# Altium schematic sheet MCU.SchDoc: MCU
size A3; CompanyName: Hitex GmbH; Address1: Greschbachstr. 12; Address2: 76229 Karlsruhe, Germany; Address3: www.hitex.com; DocumentNumber: 2; SheetNumber: 9; SheetTotal: 9; PageSetup: Record=PageOptions¦CenterHorizontal=True¦CenterVertical=True¦PrintScale=1.04¦XCorrection=1.00¦YCorrection=1.00¦PrintKind=0¦BorderSize=5000000¦LeftOffset=0¦BottomOffset=0¦Orientation=2¦PaperLength=1000¦PaperWidth=1000¦Scale=100¦PaperSource=7¦PrintQuality=1200¦MediaType=1¦DitherType=10¦PaperKind=A3¦PrintScaleMode=1
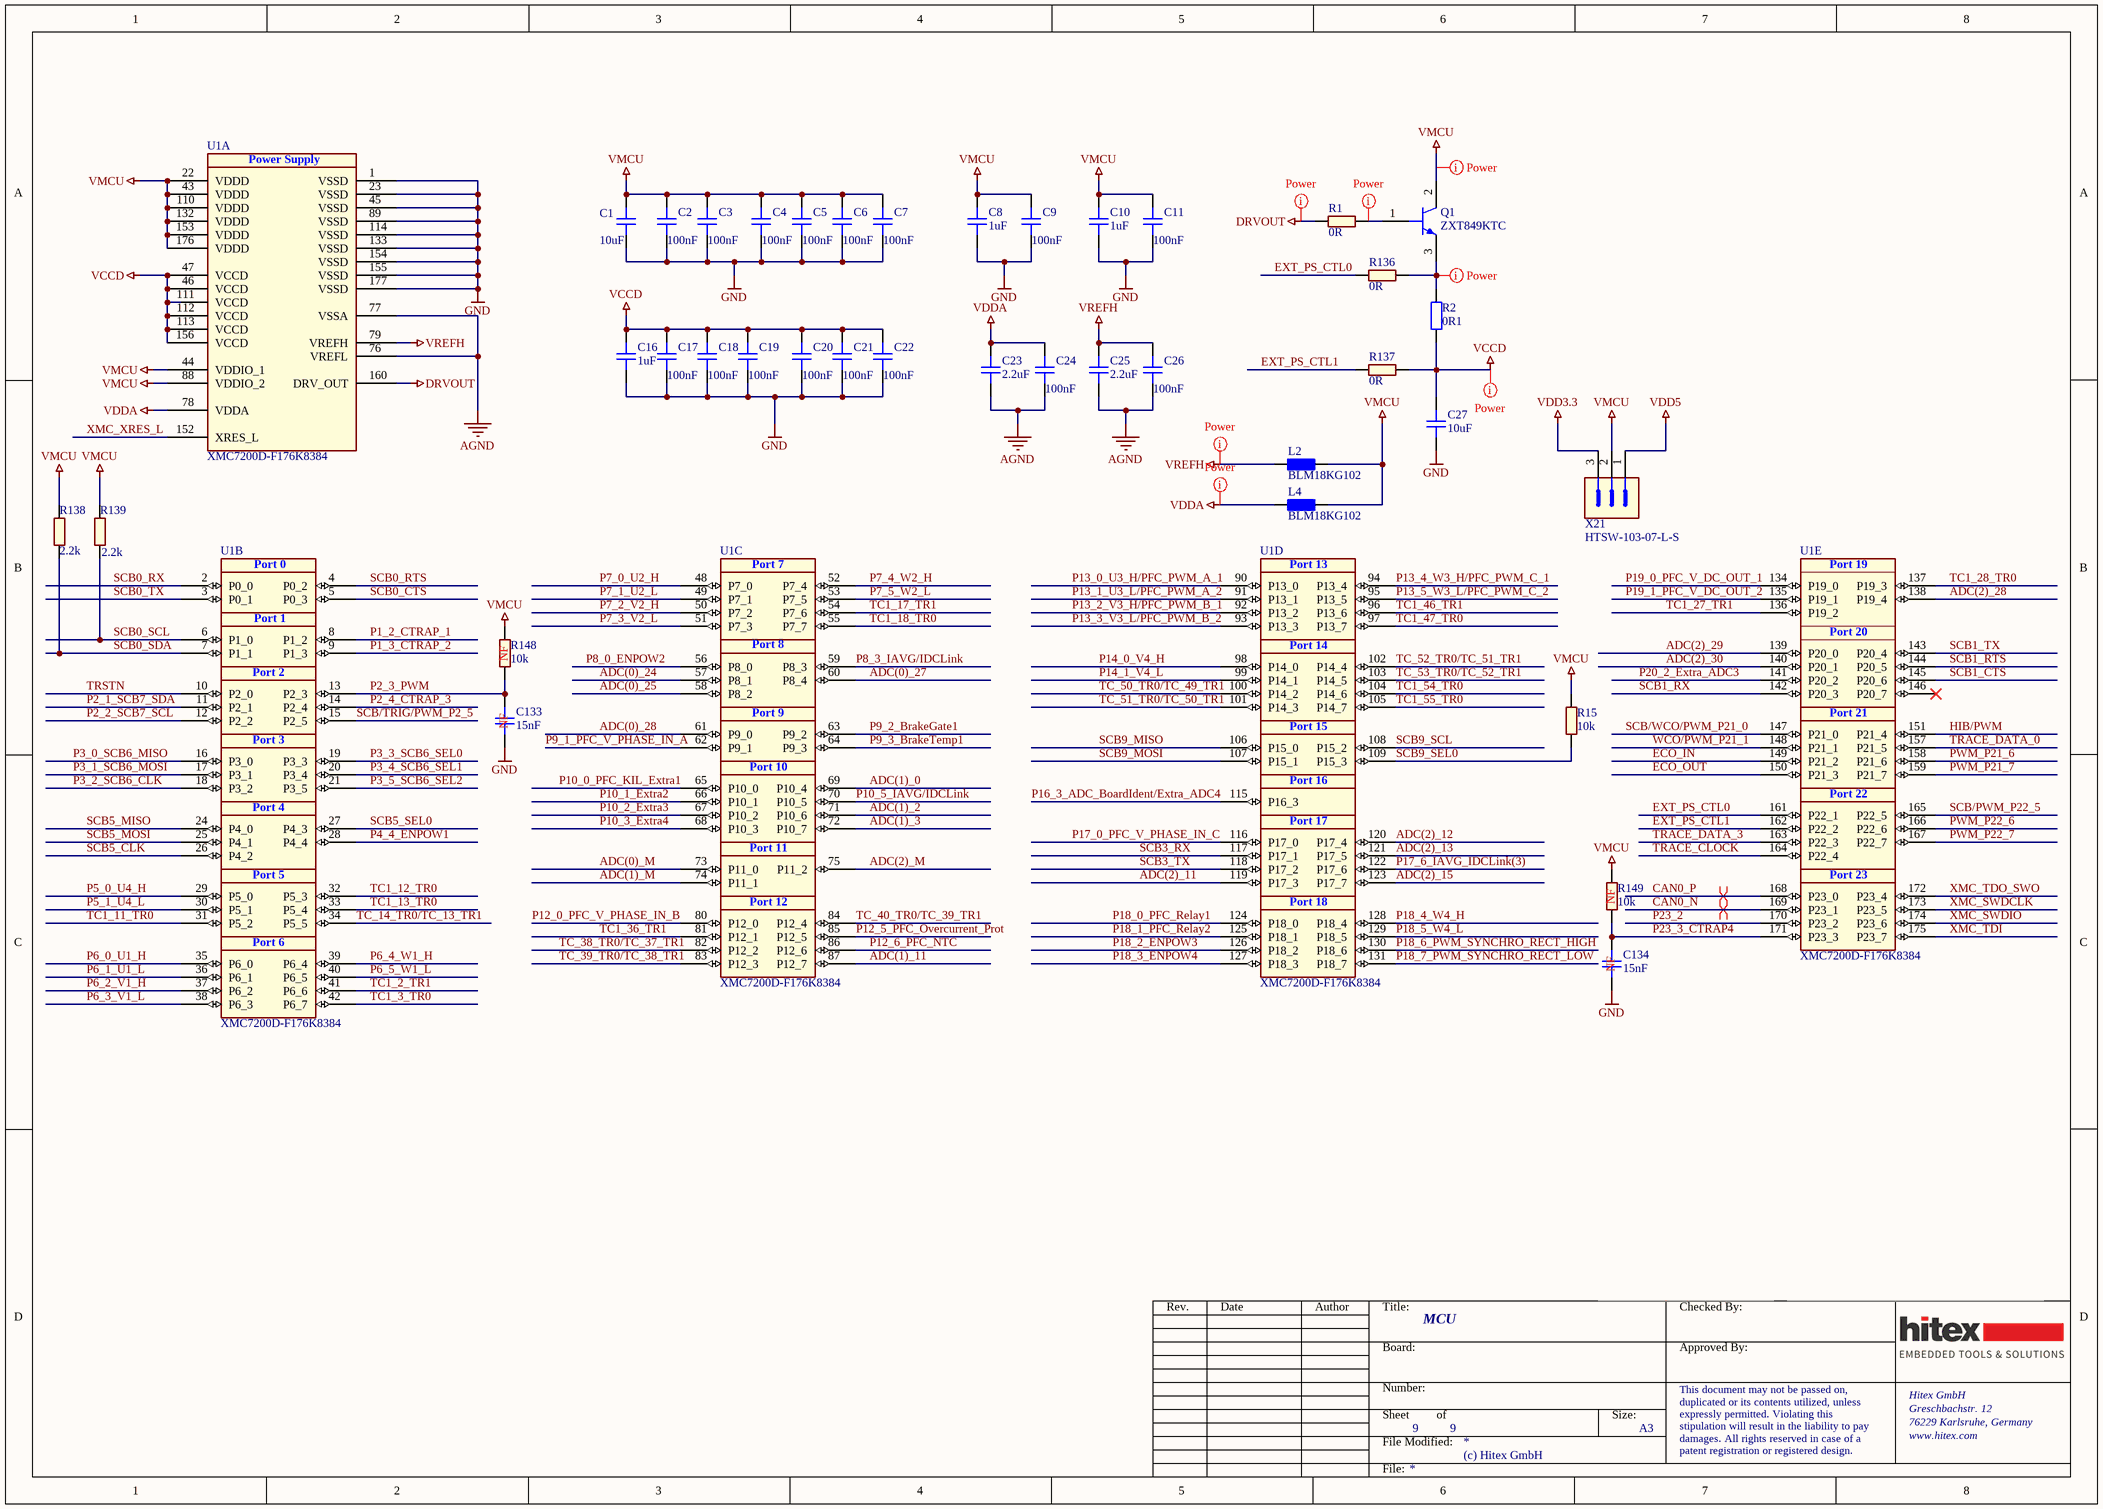
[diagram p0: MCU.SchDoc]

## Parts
C1  10uF  [CAPC3216X180N]
C2  100nF  [CAPC1005X60N]
C3  100nF  [CAPC1005X60N]
C4  100nF  [CAPC1005X60N]
C5  100nF  [CAPC1005X60N]
C6  100nF  [CAPC1005X60N]
C7  100nF  [CAPC1005X60N]
C8  1uF  [CAPC1608X90N-1]
C9  100nF  [CAPC1005X60N]
C10  1uF  [CAPC1608X90N-1]
C11  100nF  [CAPC1005X60N]
C16  1uF  [CAPC1608X90N-1]
C17  100nF  [CAPC1005X60N]
C18  100nF  [CAPC1005X60N]
C19  100nF  [CAPC1005X60N]
C20  100nF  [CAPC1005X60N]
C21  100nF  [CAPC1005X60N]
C22  100nF  [CAPC1005X60N]
C23  2.2uF  [CAPC2013X140N-1]
C24  100nF  [CAPC1005X60N]
C25  2.2uF  [CAPC2013X140N-1]
C26  100nF  [CAPC1005X60N]
C27  10uF  [CAPC3216X180N]
C133  15nF  [CAPC1005X55N-0]
C134  15nF  [CAPC1005X55N-0]
L2  BLM18KG102  [INDC1608N]
L4  BLM18KG102  [INDC1608N]
Q1  ZXT849KTC  [TO229P991X252-3N]
R1  0R  [RESC1005X03N]
R2  0R1  [RESC3216N]
R15  10k  [RESC1005X40N]
R136  0R  [RESC1005X03N]
R137  0R  [RESC1005X03N]
R138  2.2k  [RESC1005X40N]
R139  2.2k  [RESC1005X40N]
R148  10k  [RESC1005X40N]
R149  10k  [RESC1005X40N]
U1  XMC7200D-F176K8384  [QFP50P2600X2600X170-177N]  (parts A,B,C,D,E of 5)
X21  HTSW-103-07-L-S  [CON-M-THT-HTSW-103-07-L-S]

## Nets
AGND: C23.1 C24.1 C25.1 C26.1 U1.76(VREFL) U1.77(VSSA)
DRVOUT: R1.1 U1.160(DRV_OUT)
GND: C1.1 C2.1 C3.1 C4.1 C5.1 C6.1 C7.1 C8.1 C9.1 C10.1 C11.1 C16.1 C17.1 C18.1 C19.1 C20.1 C21.1 C22.1 C27.1 C133.2 C134.2 U1.1(VSSD) U1.23(VSSD) U1.45(VSSD) U1.89(VSSD) U1.114(VSSD) U1.133(VSSD) U1.154(VSSD) U1.155(VSSD) U1.177(VSSD)
VCCD: C16.2 C17.2 C18.2 C19.2 C20.2 C21.2 C22.2 C27.2 R2.1 R137.2 U1.46(VCCD) U1.47(VCCD) U1.111(VCCD) U1.112(VCCD) U1.113(VCCD) U1.156(VCCD)
VDD3.3: X21.3
VDD5: X21.1
VDDA: C23.2 C24.2 L4.1 U1.78(VDDA)
VMCU: C1.2 C2.2 C3.2 C4.2 C5.2 C6.2 C7.2 C8.2 C9.2 C10.2 C11.2 L2.2 L4.2 Q1.2(COLLECTOR) R15.2 R138.2 R139.2 R148.2 R149.2 U1.22(VDDD) U1.43(VDDD) U1.44(VDDIO_1) U1.88(VDDIO_2) U1.110(VDDD) U1.132(VDDD) U1.153(VDDD) U1.176(VDDD) X21.2
VREFH: C25.2 C26.2 L2.1 U1.79(VREFH)
ADC(0)_24: U1.57(P8_1)
ADC(0)_25: U1.58(P8_2)
ADC(0)_27: U1.60(P8_4)
ADC(0)_28: U1.61(P9_0)
ADC(0)_M: U1.73(P11_0)
ADC(1)_0: U1.69(P10_4)
ADC(1)_2: U1.71(P10_6)
ADC(1)_3: U1.72(P10_7)
ADC(1)_11: U1.87(P12_7)
ADC(1)_M: U1.74(P11_1)
ADC(2)_11: U1.119(P17_3)
ADC(2)_12: U1.120(P17_4)
ADC(2)_13: U1.121(P17_5)
ADC(2)_15: U1.123(P17_7)
ADC(2)_28: U1.138(P19_4)
ADC(2)_29: U1.139(P20_0)
ADC(2)_30: U1.140(P20_1)
ADC(2)_M: U1.75(P11_2)
CAN0_N: U1.169(P23_1)
CAN0_P: U1.168(P23_0)
ECO_IN: U1.149(P21_2)
ECO_OUT: U1.150(P21_3)
EXT_PS_CTL0: R136.1 U1.161(P22_1)
EXT_PS_CTL1: R137.1 U1.162(P22_2)
HIB/PWM: U1.151(P21_4)
P1_2_CTRAP_1: U1.8(P1_2)
P1_3_CTRAP_2: U1.9(P1_3)
P2_1_SCB7_SDA: U1.11(P2_1)
P2_2_SCB7_SCL: U1.12(P2_2)
P2_3_PWM: C133.1 R148.1 U1.13(P2_3)
P2_4_CTRAP_3: U1.14(P2_4)
P3_0_SCB6_MISO: U1.16(P3_0)
P3_1_SCB6_MOSI: U1.17(P3_1)
P3_2_SCB6_CLK: U1.18(P3_2)
P3_3_SCB6_SEL0: U1.19(P3_3)
P3_4_SCB6_SEL1: U1.20(P3_4)
P3_5_SCB6_SEL2: U1.21(P3_5)
P4_4_ENPOW1: U1.28(P4_4)
P5_0_U4_H: U1.29(P5_0)
P5_1_U4_L: U1.30(P5_1)
P6_0_U1_H: U1.35(P6_0)
P6_1_U1_L: U1.36(P6_1)
P6_2_V1_H: U1.37(P6_2)
P6_3_V1_L: U1.38(P6_3)
P6_4_W1_H: U1.39(P6_4)
P6_5_W1_L: U1.40(P6_5)
P7_0_U2_H: U1.48(P7_0)
P7_1_U2_L: U1.49(P7_1)
P7_2_V2_H: U1.50(P7_2)
P7_3_V2_L: U1.51(P7_3)
P7_4_W2_H: U1.52(P7_4)
P7_5_W2_L: U1.53(P7_5)
P8_0_ENPOW2: U1.56(P8_0)
P8_3_IAVG/IDCLink: U1.59(P8_3)
P9_1_PFC_V_PHASE_IN_A: U1.62(P9_1)
P9_2_BrakeGate1: U1.63(P9_2)
P9_3_BrakeTemp1: U1.64(P9_3)
P10_0_PFC_KIL_Extra1: U1.65(P10_0)
P10_1_Extra2: U1.66(P10_1)
P10_2_Extra3: U1.67(P10_2)
P10_3_Extra4: U1.68(P10_3)
P10_5_IAVG/IDCLink: U1.70(P10_5)
P12_0_PFC_V_PHASE_IN_B: U1.80(P12_0)
P12_5_PFC_Overcurrent_Prot: U1.85(P12_5)
P12_6_PFC_NTC: U1.86(P12_6)
P13_0_U3_H/PFC_PWM_A_1: U1.90(P13_0)
P13_1_U3_L/PFC_PWM_A_2: U1.91(P13_1)
P13_2_V3_H/PFC_PWM_B_1: U1.92(P13_2)
P13_3_V3_L/PFC_PWM_B_2: U1.93(P13_3)
P13_4_W3_H/PFC_PWM_C_1: U1.94(P13_4)
P13_5_W3_L/PFC_PWM_C_2: U1.95(P13_5)
P14_0_V4_H: U1.98(P14_0)
P14_1_V4_L: U1.99(P14_1)
P16_3_ADC_BoardIdent/Extra_ADC4: U1.115(P16_3)
P17_0_PFC_V_PHASE_IN_C: U1.116(P17_0)
P17_6_IAVG_IDCLink(3): U1.122(P17_6)
P18_0_PFC_Relay1: U1.124(P18_0)
P18_1_PFC_Relay2: U1.125(P18_1)
P18_2_ENPOW3: U1.126(P18_2)
P18_3_ENPOW4: U1.127(P18_3)
P18_4_W4_H: U1.128(P18_4)
P18_5_W4_L: U1.129(P18_5)
P18_6_PWM_SYNCHRO_RECT_HIGH: U1.130(P18_6)
P18_7_PWM_SYNCHRO_RECT_LOW: U1.131(P18_7)
P19_0_PFC_V_DC_OUT_1: U1.134(P19_0)
P19_1_PFC_V_DC_OUT_2: U1.135(P19_1)
P20_2_Extra_ADC3: U1.141(P20_2)
P23_2: U1.170(P23_2)
P23_3_CTRAP4: C134.1 R149.1 U1.171(P23_3)
PWM_P21_6: U1.158(P21_6)
PWM_P21_7: U1.159(P21_7)
PWM_P22_6: U1.166(P22_6)
PWM_P22_7: U1.167(P22_7)
SCB0_CTS: U1.5(P0_3)
SCB0_RTS: U1.4(P0_2)
SCB0_RX: U1.2(P0_0)
SCB0_SCL: R139.1 U1.6(P1_0)
SCB0_SDA: R138.1 U1.7(P1_1)
SCB0_TX: U1.3(P0_1)
SCB1_CTS: U1.145(P20_6)
SCB1_RTS: U1.144(P20_5)
SCB1_RX: U1.142(P20_3)
SCB1_TX: U1.143(P20_4)
SCB3_RX: U1.117(P17_1)
SCB3_TX: U1.118(P17_2)
SCB5_CLK: U1.26(P4_2)
SCB5_MISO: U1.24(P4_0)
SCB5_MOSI: U1.25(P4_1)
SCB5_SEL0: U1.27(P4_3)
SCB9_MISO: U1.106(P15_0)
SCB9_MOSI: U1.107(P15_1)
SCB9_SCL: U1.108(P15_2)
SCB9_SEL0: R15.1 U1.109(P15_3)
SCB/PWM_P22_5: U1.165(P22_5)
SCB/TRIG/PWM_P2_5: U1.15(P2_5)
SCB/WCO/PWM_P21_0: U1.147(P21_0)
TC1_2_TR1: U1.41(P6_6)
TC1_3_TR0: U1.42(P6_7)
TC1_11_TR0: U1.31(P5_2)
TC1_12_TR0: U1.32(P5_3)
TC1_13_TR0: U1.33(P5_4)
TC1_17_TR1: U1.54(P7_6)
TC1_18_TR0: U1.55(P7_7)
TC1_27_TR1: U1.136(P19_2)
TC1_28_TR0: U1.137(P19_3)
TC1_36_TR1: U1.81(P12_1)
TC1_46_TR1: U1.96(P13_6)
TC1_47_TR0: U1.97(P13_7)
TC1_54_TR0: U1.104(P14_6)
TC1_55_TR0: U1.105(P14_7)
TC_14_TR0/TC_13_TR1: U1.34(P5_5)
TC_38_TR0/TC_37_TR1: U1.82(P12_2)
TC_39_TR0/TC_38_TR1: U1.83(P12_3)
TC_40_TR0/TC_39_TR1: U1.84(P12_4)
TC_50_TR0/TC_49_TR1: U1.100(P14_2)
TC_51_TR0/TC_50_TR1: U1.101(P14_3)
TC_52_TR0/TC_51_TR1: U1.102(P14_4)
TC_53_TR0/TC_52_TR1: U1.103(P14_5)
TRACE_CLOCK: U1.164(P22_4)
TRACE_DATA_0: U1.157(P21_5)
TRACE_DATA_3: U1.163(P22_3)
TRSTN: U1.10(P2_0)
WCO/PWM_P21_1: U1.148(P21_1)
XMC_SWDCLK: U1.173(P23_5)
XMC_SWDIO: U1.174(P23_6)
XMC_TDI: U1.175(P23_7)
XMC_TDO_SWO: U1.172(P23_4)
XMC_XRES_L: U1.152(XRES_L)
NetQ1_1: Q1.1(BASE) R1.2
NetQ1_3: Q1.3(EMITTER) R2.2 R136.2

Not connected (* = marked no-connect by the designer): U1 146(P20_7)*

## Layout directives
net class Power: DRVOUT, NetQ1_1, NetQ1_3, VCCD, VDDA, VMCU, VREFH
differential pair: CAN0_N, CAN0_P

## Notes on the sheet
- (near R148) NF
- (near C133) NF
- (near R149) NF
- (near C134) NF

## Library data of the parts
C1 C27 = 282249: CAP / CERA / 10uF / 50V / 20% / X5R (EIA) / -55°C to 85°C / 1206(3216) / SMD / -; Multiple Parts: No; Manufacturer: MuRata; Manufacturer Order Number: GRM31CR61H106MA12L; Symbol Type: Capacitor; Single; Standard; 2 Pins; Alternate View: Yes; Article Number: 282249; Version Number: V01; Combined Parameters: TC:X5R (EIA);Tol.:-20%/+20%;Vdc:50V; QuickPick: 10uF / 50V / 20% / X5R (EIA) / 1206 (3216); Type: Standard; Style: Single; Package Metric: 3216; Package Imperial: 1206; ComponentStatus: Released; PLMStatus: Not Recommended For New Designs
C2-C7 C9 C11 C17-C22 C24 C26 = 507459: CAP / CERA / 100nF / 50V / 10% / X7R (EIA) / -55°C to 125°C / 0402(1005) / SMD / -; Multiple Parts: No; Manufacturer: TDK Corporation; Manufacturer Order Number: C1005X7R1H104K050BE; Symbol Type: Capacitor; Single; Standard; 2 Pins; Alternate View: Yes; Article Number: 507459; Version Number: V01; Combined Parameters: TC:X7R (EIA);Tol.:-10%/+10%;Vdc:50V; QuickPick: 100nF / 50V / 10% / X7R (EIA) / 0402 (1005); Type: Standard; Style: Single; Package Metric: 1005; Package Imperial: 0402; ComponentStatus: Released; PLMStatus: Active
C8 C10 C16 = 668123: CAP / CERA / 1uF / 25V / 10% / X7R (EIA) / -55°C to 125°C / 0603(1608) / SMD / -; Multiple Parts: No; Manufacturer: Samsung; Manufacturer Order Number: CL10B105KA8NNNC; Symbol Type: Capacitor; Single; Standard; 2 Pins; Alternate View: Yes; Article Number: 668123; Version Number: V01; Combined Parameters: TC:X7R (EIA);Tol.:-10%/+10%;Vdc:25V; QuickPick: 1uF / 25V / 10% / X7R (EIA) / 0603 (1608); Type: Standard; Style: Single; Package Metric: 1608; Package Imperial: 0603; ComponentStatus: Released; PLMStatus: Active
C23 C25 = 251112: CAP / CERA / 2.2uF / 16V / 10% / X7R (EIA) / -55°C to 125°C / 0805(2012) / SMD / -; Multiple Parts: No; Manufacturer: Kemet; Manufacturer Order Number: C0805C225K4RAC; Symbol Type: Capacitor; Single; Standard; 2 Pins; Alternate View: Yes; Article Number: 251112; Version Number: V01; Combined Parameters: TC:X7R (EIA);Tol.:-10%/+10%;Vdc:16V; QuickPick: 2.2uF / 16V / 10% / X7R (EIA) / 0805 (2012); Type: Standard; Style: Single; Package Metric: 2012; Package Imperial: 0805; ComponentStatus: Released; PLMStatus: Active
C133 C134 = 289336: CAP / CERA / 15nF / 50V / 20% / X7R (EIA) / -55°C to 125°C / 0402(1005) / SMD / -; Multiple Parts: No; Legacy PartNumber: CAP01006940; Manufacturer: MuRata; Manufacturer Order Number: GCM155R71H153MA55; Symbol Type: Capacitor; Single; Standard; 2 Pins; Alternate View: Yes; Article Number: 289336; Version Number: V01; Combined Parameters: TC:X7R (EIA);Tol.:-20%/+20%;Vdc:50V; QuickPick: 15nF / 50V / 20% / X7R (EIA) / 0402 (1005); Type: Standard; Style: Single; Automotive Qualified: AEC Q200; Package Metric: 1005; Package Imperial: 0402; ComponentStatus: Released; PLMStatus: Active
L2 L4 = BLM18KG102SN1D: FERRITE, SMD, 1000 OHM, 0.8A, 0603; PartNumber: 01.30.0521.0; Manufacturer: Murata; Designer: Th; CheckOrientation: false
Q1 = 612600: NPN Low Saturation  Power Transistor, BVCBO 80V, BVCEO 30V; Manufacturer: Diodes Incorporated; Symbol type: Bipolar Junction Transistor (BJT), Pin 1 Base, 2 Collector, 3 Emitter, 3 Pins; Article Number: 612600; Version Number: V01; Legacy DeviceID: DI_ZXT849KTC; Combined Parameters: NPN;Uce:30V;Ic:7A;P:33.6W;F:-; QuickPick: NPN / 33.6W / 7A / 30V / TO252(DPAK); Style: Single; Automotive Qualified: AEC Q101; ComponentStatus: Released; PLMStatus: Active; Second Source allowed: Yes; Voltage DC (max): na
R1 R136 R137 = 327372: RES / STD / 0R / 63mW / 0R / 0ppm/K / -55°C to 155°C / 0402(1005) / SMD / -; Multiple Parts: No; Legacy PartNumber: RES00000001; Manufacturer: Yageo; Manufacturer Order Number: RC0402JR-070RL; Symbol Type: Resistor; Single; Standard; 2 Pins; Alternate View: Yes; Article Number: 327372; Version Number: V01; Combined Parameters: TCR:0ppm/K;Tol.:-0R/+0R;Vdc:50V;Idc:1A;P:63mW; QuickPick: 0R / 0R / 0.063 / 0402 (1005); Style: Single; Package Metric: 1005; Package Imperial: 0402; ComponentStatus: Released; PLMStatus: Active; Voltage DC (max): 50V
R2 = 0R1: 1%, 0.25W; PartNumber: 01.02.0096.0; Designer: Ma; CheckOrientation: false
R15 R148 R149 = 342167: RES / STD / 10k / 63mW / 1% / 100ppm/K / -55°C to 155°C / 0402(1005) / SMD / -; Multiple Parts: No; Legacy PartNumber: RES01800457; Manufacturer: Vishay; Manufacturer Order Number: CRCW040210K0FK; Symbol Type: Resistor; Single; Standard; 2 Pins; Alternate View: Yes; Article Number: 342167; Version Number: V01; Combined Parameters: TCR:100ppm/K;Tol.:-1%/+1%;Vdc:50V;Idc:-;P:63mW; QuickPick: 10k / 1% / 0.063 / 0402 (1005); Style: Single; Automotive Qualified: AEC Q200; Package Metric: 1005; Package Imperial: 0402; ComponentStatus: Released; PLMStatus: Active; Voltage DC (max): 50V
R138 R139 = 341777: RES / STD / 2.2k / 63mW / 1% / 100ppm/K / -55°C to 155°C / 0402(1005) / SMD / -; Multiple Parts: No; Legacy PartNumber: RES01800379; Manufacturer: Vishay; Manufacturer Order Number: CRCW04022K20FK; Symbol Type: Resistor; Single; Standard; 2 Pins; Alternate View: Yes; Article Number: 341777; Version Number: V01; Combined Parameters: TCR:100ppm/K;Tol.:-1%/+1%;Vdc:50V;Idc:-;P:63mW; QuickPick: 2.2k / 1% / 0.063 / 0402 (1005); Style: Single; Automotive Qualified: AEC Q200; Package Metric: 1005; Package Imperial: 0402; ComponentStatus: Released; PLMStatus: Active; Voltage DC (max): 50V
U1 = CYT4BF8CEE: 32-bit Arm Cortex-M7 Microcontroller Traveo II Family; Multiple Parts: Yes; Manufacturer: Infineon Technologies; Alternate View: No; Product Name: IFX_XMC7200D-F176K8384; Pins Electrical: 177; Temperature (min.) [°C]: -40; Temperature (max.) [°C]: 150; Component Height (max.)  [mm]: 1.7mm; Digital Supply Voltage (min.) [V]: 2.7V; Digital Supply Voltage (max.) [V]: 5.5V; Clock Frequency (max.): 32MHz; RAM: 1MB; ROM: 64kB; Flash: 256kB; Core Architecture: ARM Cortex-M0; DMA Channels: 216; Interfaces: MAC, MII, RMII, RGMII, I2S; No Of I/Os (max.): 99; No Of Cores: 2; ComponentStatus: Created; Description (long): XMC7200 is a family of XMC7000 microcontrollers targeted at industrial applications. XMC7200 has two Arm Cortex-M7 CPUs for primary processing, and an Arm Cortex-M0+ CPU for peripheral and security processing; PLM Status: Preliminary
X21 = 378477: Through hole .025 SQ Post Header, 2.54mm pitch, 3 pin, vertical, single row; Legacy PartNumber: CON01500137; Manufacturer: Samtec; Article Number: 378477; Version Number: V01; Legacy DeviceID: SAM_HTSW-103-07-L-S; Combined Parameters: Board-to-Board Header (male);3x1;Mounting:THT;Orient:0° (vertical);Shielded:No; QuickPick: 0° (vertical) / Board-to-Board; Style: Strip; Automotive Qualified: No; ComponentStatus: Released; PLMStatus: Active; Second Source allowed: Yes; Voltage DC (max): na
